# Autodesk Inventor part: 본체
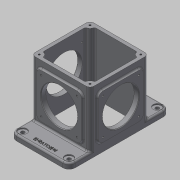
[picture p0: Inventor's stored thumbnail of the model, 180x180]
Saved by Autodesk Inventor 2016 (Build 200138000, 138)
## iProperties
Created: 2018-09
Part Number: 본체
Material: 일반
Document SubType Name: Modeling
Designer: mduedu
Density: 1 g/cm^3
Appearance: 기본값
Author: mduedu
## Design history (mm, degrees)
sketch "스케치1"
  geometry: L1 (90, 52.5)-(-90, 52.5); L2 (-90, 52.5)-(-90, -52.5); L3 (-90, -52.5)-(90, -52.5); L4 (90, -52.5)-(90, 52.5); L5 (90, 52.5)-(-90, -52.5); L6 (-90, 52.5)-(90, -52.5); 1 further point
  constraints: 12 end point, 2 midpoint, 2 parallel, 1 horizontal, 1 perpendicular
  dimensions: "d0" = 180 distance of L3.end L2.end; "d1" = 105 distance of L2.end L1.end
extrude "돌출1" new body sketch "스케치1" distance "d2" = 10; taper "d3" = 0 deg
sketch "스케치2"
  geometry: L1 (-52.5, -52.5)-(52.5, -52.5); L2 (52.5, -52.5)-(52.5, 52.5); L3 (52.5, 52.5)-(-52.5, 52.5); L4 (-52.5, 52.5)-(-52.5, -52.5); L5 (-52.5, -52.5)-(52.5, 52.5); L6 (52.5, -52.5)-(-52.5, 52.5); 1 further point
  constraints: 12 end point, 2 midpoint, 2 parallel, 1 horizontal, 1 perpendicular
  dimensions: "d4" = 105 distance of L3.end L2.end; "d5" = 105 distance of L2.end L1.end
extrude "돌출2" join sketch "스케치2" distance "d6" = 100; taper "d7" = 0 deg
sketch "스케치14"
  geometry: L1 (-52.5, 52.5)-(52.5, 52.5) reference; L2 (52.5, 52.5)-(52.5, -52.5) reference; L3 (52.5, -52.5)-(-52.5, -52.5) reference; L4 (-52.5, -52.5)-(-52.5, 52.5) reference; L5 (46.5, 46.5)-(-46.5, 46.5); L6 (-46.5, 46.5)-(-46.5, -46.5); L7 (-46.5, -46.5)-(46.5, -46.5); L8 (46.5, -46.5)-(46.5, 46.5); 1 further point
  constraints: 8 end point, 3 other
  dimensions: "d85" = 6 distance between parallel lines of L5 L1
extrude "돌출10" cut sketch "스케치14" stored distance "d86" = 10; taper "d87" = 0 deg
fillet "모깎기1" dims "d12" = 7
sketch "스케치15"
  geometry: A1 r 7 centre (-45.5, 45.5) between (-45.5, 52.5) and (-52.5, 45.5) reference; A2 r 7 centre (45.5, 45.5) between (52.5, 45.5) and (45.5, 52.5) reference; A3 r 7 centre (45.5, -45.5) between (45.5, -52.5) and (52.5, -45.5) reference; A4 r 7 centre (-45.5, -45.5) between (-52.5, -45.5) and (-45.5, -52.5) reference; 5 further points
  constraints: 4 coincident, 4 vertical alignment, 8 other
extrude "돌출11" join sketch "스케치15" stored distance "d88" = 10; taper "d89" = 0 deg
fillet "모깎기15" dims "d90" = 3
sketch "스케치6"
  geometry: L1 (50, 17.5)-(130, 17.5); L2 (130, 17.5)-(130, 97.5); L3 (130, 97.5)-(50, 97.5); L4 (50, 97.5)-(50, 17.5); L5 (50, 17.5)-(130, 97.5); L6 (130, 17.5)-(50, 97.5); L7 (0, 0)-(180, 0) reference; 4 further points
  constraints: 12 end point, 4 midpoint, 2 parallel, 1 horizontal, 1 perpendicular, 1 vertical alignment
  dimensions: "d25" = 80 distance of L3.end L2.end; "d26" = 80 distance of L2.end L1.end; "d27" = 57.5 distance of point (90, 0) point (90, 57.5)
extrude "돌출6" join sketch "스케치6" distance "d28" = 3; taper "d29" = 0 deg
fillet "모깎기7" dims "d30" = 8
sketch "스케치7"
  geometry: C1 r 32.5 at (90, 57.5); 1 further point
  constraints: 1 centre point, 1 vertical alignment
  dimensions: "d32" = 65 diameter of C1; "d33" = 57.5 distance of C1.centre point (90, 0)
extrude "돌출7" cut sketch "스케치7" stored distance "d34" = 3; taper "d35" = 0 deg
fillet "모깎기9" dims "d36" = 3
sketch "스케치8"
  geometry: L1 (5.5, 7.5)-(85.5, 7.5); L2 (85.5, 7.5)-(85.5, 87.5); L3 (85.5, 87.5)-(5.5, 87.5); L4 (5.5, 87.5)-(5.5, 7.5); L5 (5.5, 7.5)-(85.5, 87.5); L6 (85.5, 7.5)-(5.5, 87.5); L7 (-7, -10)-(98, -10) reference; C1 r 32.5 at (45.5, 47.5); 4 further points
  constraints: 12 end point, 4 midpoint, 2 parallel, 1 centre point, 1 coincident, 1 horizontal, 1 perpendicular, 1 vertical alignment
  dimensions: "d37" = 80 distance of L3.end L2.end; "d38" = 80 distance of L2.end L1.end; "d39" = 57.5 distance from line of point (45.5, 47.5) L7; "d40" = 65 diameter of C1
extrude "돌출8" join sketch "스케치8" distance "d41" = 3; taper "d42" = 0 deg
fillet "모깎기10" dims "d43" = 8
extrude "돌출9" cut sketch "스케치8" stored distance "d44" = 3; taper "d45" = 0 deg
fillet "모깎기11" dims "d46" = 3
sketch "스케치9"
  geometry: L1 (50, 89.5)-(50, 25.5) reference; L2 (58, 17.5)-(122, 17.5) reference; L3 (130, 25.5)-(130, 89.5) reference; L4 (122, 97.5)-(58, 97.5) reference; C1 r 32.5 at (90, 57.5) reference; A1 r 8 centre (58, 89.5) between (58, 97.5) and (50, 89.5) reference; A2 r 8 centre (58, 25.5) between (50, 25.5) and (58, 17.5) reference; A3 r 8 centre (122, 25.5) between (122, 17.5) and (130, 25.5) reference; A4 r 8 centre (122, 89.5) between (130, 89.5) and (122, 97.5) reference; 5 further points
  constraints: 4 coincident
hole "구멍1" sketch "스케치9" at (58, 89.5), (122, 89.5), (122, 25.5), (58, 25.5) diameter "d47" = 3.242; stored, may be unused: countersink angle "d51" = 90 deg, drill point angle "d53" = 118 deg; dims "d48" = 6, "d49" = 4, "d50" = 2, "d52" = 9
sketch "스케치10" dims "d30" = 8
  geometry: L1 (13.5, 7.5)-(77.5, 7.5) reference; L2 (85.5, 15.5)-(85.5, 79.5) reference; L3 (77.5, 87.5)-(13.5, 87.5) reference; L4 (5.5, 79.5)-(5.5, 15.5) reference; C1 r 32.5 at (45.5, 47.5) reference; A1 r 8 centre (13.5, 15.5) between (5.5, 15.5) and (13.5, 7.5) reference; A2 r 8 centre (77.5, 15.5) between (77.5, 7.5) and (85.5, 15.5) reference; A3 r 8 centre (77.5, 79.5) between (85.5, 79.5) and (77.5, 87.5) reference; A4 r 8 centre (13.5, 79.5) between (13.5, 87.5) and (5.5, 79.5) reference; 5 further points
  constraints: 4 coincident
hole "구멍2" sketch "스케치10" at (13.5, 79.5), (77.5, 79.5), (77.5, 15.5), (13.5, 15.5) diameter "d54" = 3.242; stored, may be unused: countersink angle "d58" = 90 deg, drill point angle "d60" = 118 deg; dims "d30" = 8, "d55" = 6, "d56" = 4, "d57" = 2, "d59" = 9
fillet "모깎기12" dims "d68" = 11
sketch "스케치16"
  geometry: A1 r 11 centre (-79, 41.5) between (-79, 52.5) and (-90, 41.5) reference; A2 r 11 centre (-79, -41.5) between (-90, -41.5) and (-79, -52.5) reference; A3 r 11 centre (79, 41.5) between (90, 41.5) and (79, 52.5) reference; A4 r 11 centre (79, -41.5) between (79, -52.5) and (90, -41.5) reference; 5 further points
  constraints: 4 coincident
hole "구멍5" sketch "스케치16" at (-79, 41.5), (79, 41.5), (79, -41.5), (-79, -41.5) diameter "d91" = 6.6; stored, may be unused: countersink angle "d95" = 90 deg, drill point angle "d97" = 118 deg; dims "d92" = 6, "d93" = 15, "d94" = 2, "d96" = 8
fillet "모깎기13" dims "d77" = 3
fillet "모깎기14" dims "d78" = 3
chamfer "모따기1" distance "d79" = 1; stored, may be unused: second distance "d80" = 2, angle "d81" = 45 deg
sketch "스케치17"
  geometry: A1 r 7 centre (-45.5, 45.5) between (-45.5, 52.5) and (-52.5, 45.5) reference; A2 r 7 centre (-45.5, -45.5) between (-52.5, -45.5) and (-45.5, -52.5) reference; A3 r 7 centre (45.5, -45.5) between (45.5, -52.5) and (52.5, -45.5) reference; A4 r 7 centre (45.5, 45.5) between (52.5, 45.5) and (45.5, 52.5) reference; 5 further points
  constraints: 4 coincident
hole "구멍6" sketch "스케치17" at (-45.5, 45.5), (45.5, 45.5), (45.5, -45.5), (-45.5, -45.5) diameter "d98" = 3.242; stored, may be unused: countersink angle "d102" = 90 deg, drill point angle "d104" = 118 deg; dims "d99" = 8, "d100" = 15, "d101" = 2, "d103" = 10
sketch "스케치13"
  geometry: L1 (90, -41.5)-(90, 41.5) reference; 2 further points
  constraints: 1 horizontal alignment, 1 other
  dimensions: "d82" = 10 distance from line of point (80, 0) L1
feature "엠보싱1" sketch "스케치13" dims "d0" = 180, "d1" = 105, "d25" = 80, "d26" = 80, "d27" = 57.5, "d83" = 0.5, "d84" = 0
node "솔리드1"
mirror "대칭1"
mirror "대칭2"
node "투영된 루프2"
node "투영된 루프3"
node "투영된 루프6"
